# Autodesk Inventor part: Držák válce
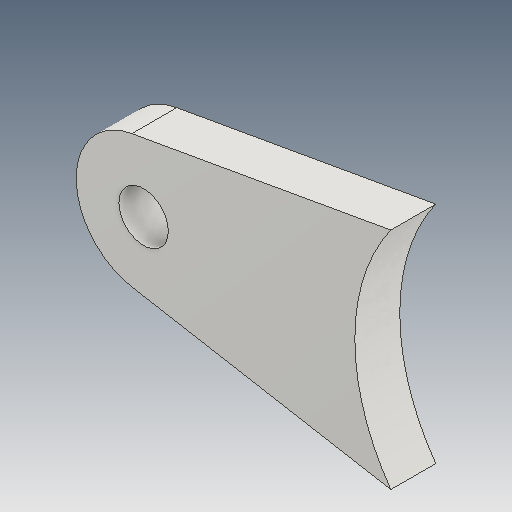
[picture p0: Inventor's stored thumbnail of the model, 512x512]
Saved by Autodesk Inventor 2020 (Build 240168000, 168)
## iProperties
Created: 2025-03
Part Number: Držák válce
Material: Ocel
Document SubType Name: Modeling
Designer: doma
Density: 7.85 g/cm^3
Appearance: Ocel
Mass: 172.678 g
Surface Area: 68.6788 cm^2
Volume: 21.9972 cm^3
Author: doma
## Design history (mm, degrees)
sketch "Náčrt1" dims "d0" = 86
  geometry: L1 (-92.622, 14.769)-(-34.986, 25); L2 (-92.622, -14.769)-(-34.986, -25); C1 r 5.5 at (-90, 0); 5 further points
  constraints: 4 end point, 2 coincident, 1 centre point, 7 other
  dimensions: "d4" = 11 diameter of C1; "d6" = 25 vertical distance of point (0, 0) L1.end
extrude "Vysunutí1" new body sketch "Náčrt1" distance "d7" = 10; taper "d8" = 0 deg
node "Těleso1"
